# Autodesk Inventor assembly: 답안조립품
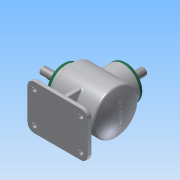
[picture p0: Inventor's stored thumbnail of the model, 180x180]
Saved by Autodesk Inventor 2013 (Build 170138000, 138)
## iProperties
Created: 2016-09
Part Number: 답안조립품
Document SubType Name: Assembly
Designer: Administrator
Author: Administrator
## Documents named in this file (14)
- C:\Users\Administrator\Desktop\460907V1014\답안조립품.iam
- C:\Users\Administrator\Desktop\460907V1014\답안부품.ipt
- C:\Users\Administrator\Desktop\460907V1014\커버.ipt
- C:\Users\Administrator\Desktop\460907V1014\베어링 6203.ipt
- C:\Users\Administrator\Desktop\460907V1014\오일실 17 32 8.ipt
- C:\Users\Administrator\Desktop\460907V1014\메인 축.ipt
- 메인 축.ipt
- C:\Users\Administrator\Desktop\460907V1014\키 5x5.ipt
- C:\Users\Administrator\Desktop\460907V1014\메인 베벨기어.ipt
- C:\Users\Administrator\Desktop\460907V1014\서브 축.ipt
- 서브 축.ipt
- C:\Users\Administrator\Desktop\460907V1014\키 4x4.ipt
- C:\Users\Administrator\Desktop\460907V1014\서브 베벨기어.ipt
- C:\Users\Administrator\Desktop\460907V1014\M4.ipt
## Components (8 placed, 1 different names)
1. M4:1
2. M4:2
3. M4:3
4. M4:4
5. M4:5
6. M4:6
7. M4:7
8. M4:8
